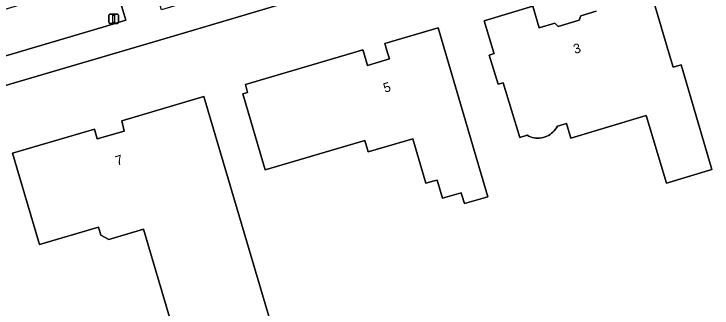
# Model space of a CAD drawing. Extents: x 162417 to 163722, y 384268 to 385417.
# Drawn here: x 163527.9 to 163601.3, y 384723.1 to 384754.1 of the extents above; entities that cross this region are included whole.
import ezdxf

# ---------------------------------------------------------------- set-up
doc = ezdxf.new("R2010")
doc.units = 0
for name, color, linetype in [('IMGEO_Erf', 7, 'Continuous'), ('IMGEO_Groenvoorziening', 7, 'Continuous'), ('IMGEO_Lichtmast', 7, 'Continuous'), ('IMGEO_Pand', 7, 'Continuous'), ('IMGEO_Pand_nummerreeks', 7, 'Continuous'), ('IMGEO_Voetpad_open', 7, 'Continuous')]:
    doc.layers.add(name, color=color, linetype=linetype)

msp = doc.modelspace()

# ---------------------------------------------------------------- linework, layer by layer
at = {"layer": 'IMGEO_Erf'}
for points in [[(163629.015, 384762.166), (163620.015, 384779.318), (163597.399, 384769.395), (163594.343, 384768.075), (163593.786, 384767.999), (163590.832, 384766.733), (163590.746, 384767.004), (163574.261, 384760.525), (163544.894, 384751.808), (163508.033, 384740.986), (163472.811, 384730.645), (163473.066, 384729.467), (163473.133, 384728.955)], [(163594.99, 384756.077), (163596.782, 384750), (163597.228, 384748.486), (163598.09, 384748.711), (163601.223, 384737.97), (163601.293, 384737.715), (163596.546, 384736.276), (163594.388, 384743.396), (163586.486, 384741.002), (163586.012, 384742.565), (163585.061, 384742.277), (163584.966, 384742.105), (163584.857, 384741.942), (163584.734, 384741.789), (163584.599, 384741.648), (163584.452, 384741.518), (163584.295, 384741.401), (163584.128, 384741.299), (163583.953, 384741.211), (163583.771, 384741.138), (163583.583, 384741.081), (163583.392, 384741.041), (163583.197, 384741.017), (163583.001, 384741.009), (163582.806, 384741.019), (163582.611, 384741.045), (163582.42, 384741.088), (163582.233, 384741.147), (163582.052, 384741.222), (163581.878, 384741.312), (163581.102, 384741.077), (163579.354, 384746.844), (163578.829, 384746.685), (163577.902, 384749.744), (163578.406, 384749.897), (163578.375, 384750), (163577.358, 384753.356), (163582.476, 384754.906), (163583.164, 384752.625), (163584.793, 384753.11), (163585.145, 384752.76), (163587.356, 384753.409), (163587.53, 384753.881), (163589.138, 384754.37)]]:
    msp.add_lwpolyline(points, dxfattribs=at)
for points in [[(163573.287, 384750), (163577.761, 384734.847), (163575.288, 384734.117), (163575.029, 384734.996), (163574.948, 384735.269), (163572.978, 384734.687), (163572.413, 384736.601), (163572.122, 384736.515), (163571.246, 384736.256), (163569.862, 384740.947), (163565.171, 384739.562), (163564.818, 384740.76), (163554.334, 384737.665), (163551.971, 384745.671), (163552.482, 384745.824), (163552.255, 384746.669), (163563.565, 384750), (163564.604, 384750.306), (163564.696, 384750), (163565.101, 384748.65), (163567.408, 384749.339), (163567.213, 384750), (163566.925, 384750.976), (163572.512, 384752.625)], [(163558.578, 384709.211), (163553.846, 384707.813), (163553.43, 384709.225), (163551.319, 384710.367), (163549.229, 384717.44), (163550.382, 384719.545), (163549.6, 384722.195), (163545.76, 384721.061), (163544.393, 384721.804), (163541.553, 384731.414), (163537.905, 384730.335), (163537.06, 384730.795), (163536.808, 384731.65), (163530.588, 384729.813), (163527.752, 384739.412), (163536.382, 384741.968), (163536.686, 384740.923), (163539.505, 384741.75), (163539.254, 384742.814), (163547.888, 384745.38)]]:
    msp.add_lwpolyline(points, close=True, dxfattribs=at)
at = {"layer": 'IMGEO_Groenvoorziening'}
msp.add_lwpolyline([(163537.254, 384752.674), (163539.698, 384753.429), (163538.627, 384756.959), (163538.37, 384757.945), (163518.228, 384751.997), (163518.558, 384750.929), (163517.538, 384750.583), (163517.216, 384751.678), (163516.394, 384751.472), (163510.098, 384749.633), (163505.104, 384748.146), (163505.416, 384747.048), (163506.448, 384743.623), (163510.906, 384744.904)], close=True, dxfattribs=at)
at = {"layer": 'IMGEO_Lichtmast'}
for p, q in [((163537.91, 384753.163), (163537.91, 384753.963)), ((163537.91, 384753.963), (163537.91, 384753.163)), ((163538.01, 384754.063), (163538.8, 384754.063)), ((163538.8, 384754.063), (163538.01, 384754.063)), ((163538.9, 384753.963), (163538.9, 384753.163)), ((163538.9, 384753.163), (163538.9, 384753.963)), ((163538.8, 384753.063), (163538.01, 384753.063)), ((163538.01, 384753.063), (163538.8, 384753.063))]:
    msp.add_line(p, q, dxfattribs=at)
msp.add_lwpolyline([(163538.33, 384753.938), (163538.48, 384753.938), (163538.48, 384753.188), (163538.33, 384753.188), (163538.33, 384753.938)], dxfattribs=at)
for centre, start, end in [((163538.01, 384753.963), 90, 180), ((163538.01, 384753.963), 90, 180), ((163538.8, 384753.963), 0, 90), ((163538.8, 384753.963), 360, 90), ((163538.01, 384753.163), 180, 270), ((163538.01, 384753.163), 180, 270), ((163538.8, 384753.163), 270, 0), ((163538.8, 384753.163), 270, 0)]:
    msp.add_arc(centre, 0.1, start, end, dxfattribs=at)
at = {"layer": 'IMGEO_Pand'}
msp.add_lwpolyline([(163589.138, 384754.37), (163587.53, 384753.881), (163587.356, 384753.409), (163585.145, 384752.76), (163584.793, 384753.11), (163583.164, 384752.625), (163582.476, 384754.906), (163577.358, 384753.356), (163578.375, 384750), (163578.406, 384749.897), (163577.902, 384749.744), (163578.829, 384746.685), (163579.354, 384746.844), (163581.102, 384741.077), (163581.878, 384741.312), (163582.052, 384741.222), (163582.233, 384741.147), (163582.42, 384741.088), (163582.611, 384741.045), (163582.806, 384741.019), (163583.001, 384741.009), (163583.197, 384741.017), (163583.392, 384741.041), (163583.583, 384741.081), (163583.771, 384741.138), (163583.953, 384741.211), (163584.128, 384741.299), (163584.295, 384741.401), (163584.452, 384741.518), (163584.599, 384741.648), (163584.734, 384741.789), (163584.857, 384741.942), (163584.966, 384742.105), (163585.061, 384742.277), (163586.012, 384742.565), (163586.486, 384741.002), (163594.388, 384743.396), (163596.546, 384736.276), (163601.293, 384737.715), (163601.223, 384737.97), (163598.09, 384748.711), (163597.228, 384748.486), (163596.782, 384750), (163594.99, 384756.077)], dxfattribs=at)
for points in [[(163573.287, 384750), (163572.512, 384752.625), (163566.925, 384750.976), (163567.213, 384750), (163567.408, 384749.339), (163565.101, 384748.65), (163564.696, 384750), (163564.604, 384750.306), (163563.565, 384750), (163552.255, 384746.669), (163552.482, 384745.824), (163551.971, 384745.671), (163554.334, 384737.665), (163564.818, 384740.76), (163565.171, 384739.562), (163569.862, 384740.947), (163571.246, 384736.256), (163572.122, 384736.515), (163572.413, 384736.601), (163572.978, 384734.687), (163574.948, 384735.269), (163575.029, 384734.996), (163575.288, 384734.117), (163577.761, 384734.847)], [(163558.578, 384709.211), (163547.888, 384745.38), (163539.254, 384742.814), (163539.505, 384741.75), (163536.686, 384740.923), (163536.382, 384741.968), (163527.752, 384739.412), (163530.588, 384729.813), (163536.808, 384731.65), (163537.06, 384730.795), (163537.905, 384730.335), (163541.553, 384731.414), (163544.393, 384721.804), (163545.76, 384721.061), (163549.6, 384722.195), (163550.382, 384719.545), (163549.229, 384717.44), (163551.319, 384710.367), (163553.43, 384709.225), (163553.846, 384707.813)]]:
    msp.add_lwpolyline(points, close=True, dxfattribs=at)
at = {"layer": 'IMGEO_Voetpad_open'}
for points in [[(163649.198, 384795.433), (163599.879, 384773.749), (163598.466, 384777.1), (163594.629, 384775.278), (163595.959, 384772.234), (163593.149, 384771.03), (163591.909, 384773.956), (163588.13, 384772.356), (163589.443, 384769.361), (163573.24, 384763.319), (163569.077, 384762.111), (163567.982, 384765.62), (163564.418, 384764.577), (163565.429, 384761.073), (163543.448, 384754.524), (163542.381, 384758.018), (163538.627, 384756.959), (163539.698, 384753.429), (163537.254, 384752.674), (163510.906, 384744.904)], [(163508.033, 384740.986), (163544.894, 384751.808), (163574.261, 384760.525), (163590.746, 384767.004), (163590.832, 384766.733), (163593.786, 384767.999), (163594.343, 384768.075), (163597.399, 384769.395), (163620.015, 384779.318), (163622.273, 384780.309), (163645.894, 384790.674)]]:
    msp.add_lwpolyline(points, dxfattribs=at)

# ---------------------------------------------------------------- texts
at = {"layer": 'IMGEO_Pand_nummerreeks'}
for s, rotation, p in [('3', 16.35795, (163586.911, 384749.86)), ('5', 16.62724, (163566.929, 384745.774)), ('7', 16.34992, (163538.755, 384738.112))]:
    msp.add_text(s, height=1, rotation=rotation, dxfattribs=at).set_placement(p)

doc.saveas('drawing.dxf')
